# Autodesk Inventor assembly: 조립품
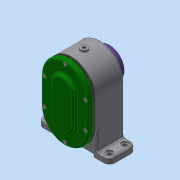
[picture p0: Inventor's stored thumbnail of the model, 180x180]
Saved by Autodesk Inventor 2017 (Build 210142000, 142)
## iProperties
Part Number: 조립품
Material: 일반
Document SubType Name: Assembly
Designer: MRC
Author: MRC
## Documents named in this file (19)
- C:\Users\MRC\Downloads\710609V1017\조립품.iam
- C:\Users\MRC\Downloads\710609V1017\본체.ipt
- C:\Users\MRC\Downloads\710609V1017\개스킷 A.ipt
- C:\Users\MRC\Downloads\710609V1017\개스킷 B.ipt
- C:\Users\MRC\Downloads\710609V1017\베어링 6001.ipt
- 베어링 6001.ipt
- C:\Users\MRC\Downloads\710609V1017\베어링 6002.ipt
- 베어링 6002.ipt
- C:\Users\MRC\Downloads\710609V1017\볼트 M4.ipt
- C:\Users\MRC\Downloads\710609V1017\스퍼기어 A.ipt
- C:\Users\MRC\Downloads\710609V1017\스퍼기어 B.ipt
- C:\Users\MRC\Downloads\710609V1017\오일 실 12 22 7.ipt
- C:\Users\MRC\Downloads\710609V1017\축 A.ipt
- C:\Users\MRC\Downloads\710609V1017\축 B.ipt
- C:\Users\MRC\Downloads\710609V1017\칼라.ipt
- C:\Users\MRC\Downloads\710609V1017\커버 A.ipt
- C:\Users\MRC\Downloads\710609V1017\커버 B.ipt
- C:\Users\MRC\Downloads\710609V1017\키 4 x 4 x 12.ipt
- C:\Users\MRC\Downloads\710609V1017\키 5 x 5 x 12.ipt
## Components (2 placed, 2 different names)
1. 개스킷 A:1
2. 개스킷 B:1
